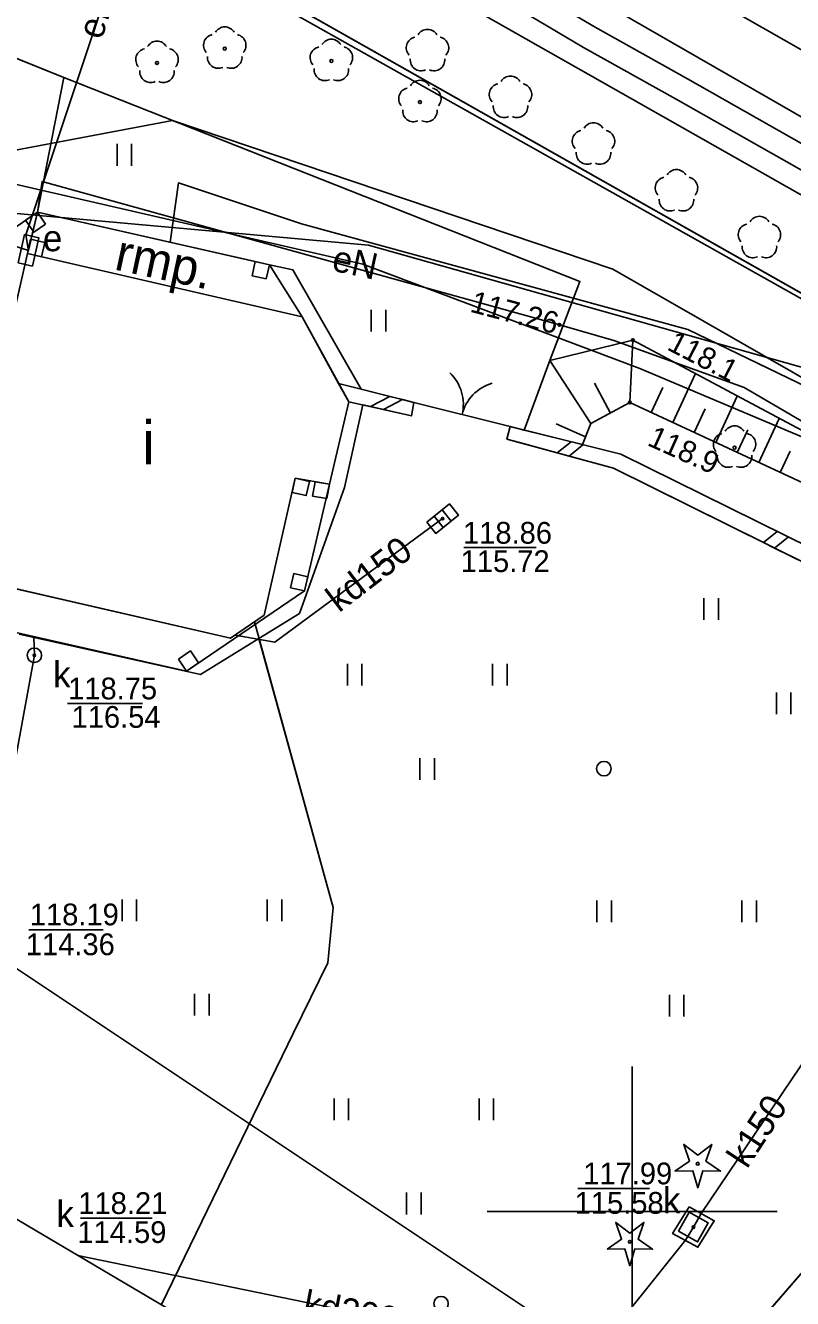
# Model space of a CAD drawing. Extents: x 6434771 to 6436222, y 5663454 to 5664782.
# Drawn here: x 6435079.09 to 6435105.53, y 5663897 to 5663940.88 of the extents above; entities that cross this region are included whole.
import ezdxf

# ---------------------------------------------------------------- set-up
doc = ezdxf.new("R2010")
doc.units = 0
for name, color, linetype in [('Warstwa 1', 7, 'Continuous'), ('Warstwa 10', 7, 'Continuous'), ('Warstwa 11', 7, 'Continuous'), ('Warstwa 12', 7, 'Continuous'), ('Warstwa 13', 7, 'Continuous'), ('Warstwa 14', 7, 'Continuous'), ('Warstwa 15', 7, 'Continuous'), ('Warstwa 2', 7, 'Continuous'), ('Warstwa 20', 7, 'Continuous'), ('Warstwa 21', 7, 'Continuous'), ('Warstwa 3', 7, 'Continuous'), ('Warstwa 31', 7, 'Continuous'), ('Warstwa 32', 7, 'Continuous'), ('Warstwa 33', 7, 'Continuous'), ('Warstwa 4', 7, 'Continuous'), ('Warstwa 5', 7, 'Continuous'), ('Warstwa 51', 7, 'Continuous'), ('Warstwa 6', 7, 'Continuous'), ('Warstwa 63', 7, 'Continuous'), ('Warstwa 7', 7, 'Continuous'), ('Warstwa 8', 7, 'Continuous'), ('Warstwa 9', 7, 'Continuous')]:
    doc.layers.add(name, color=color, linetype=linetype)

msp = doc.modelspace()

# ---------------------------------------------------------------- linework, layer by layer
at = {"layer": 'Warstwa 1'}
msp.add_line((6435069.683, 5663952.11), (6435199.169, 5663878.85), dxfattribs=at)
msp.add_line((6435069.683, 5663952.11), (6435199.169, 5663878.85), dxfattribs=at)
msp.add_lwpolyline([(6435079.153, 5663933.025), (6435076.628, 5663921.954), (6435086.153, 5663919.759), (6435087.322, 5663920.555), (6435088.39, 5663925.272), (6435089.567, 5663925.068), (6435090.232, 5663927.91), (6435088.627, 5663930.84)], close=True, dxfattribs=at)
for centre in [(6435099.029, 5663915.263), (6435093.416, 5663896.82)]:
    msp.add_circle(centre, 0.25, dxfattribs=at)
at = {"layer": 'Warstwa 10'}
for p, q in [((6435097.163, 5663929.329), (6435100.028, 5663930.032)), ((6435099.922, 5663927.883), (6435100.028, 5663930.032)), ((6435100.028, 5663930.032), (6435112.867, 5663923.176)), ((6435096.282, 5663926.934), (6435097.163, 5663929.329)), ((6435097.163, 5663929.329), (6435098.583, 5663927.159)), ((6435101.4, 5663927.195), (6435102.185, 5663928.881)), ((6435099.255, 5663927.522), (6435098.701, 5663928.547)), ((6435100.659, 5663927.54), (6435101.061, 5663928.403)), ((6435098.583, 5663927.159), (6435099.922, 5663927.883)), ((6435099.922, 5663927.883), (6435111.777, 5663922.369)), ((6435102.883, 5663926.506), (6435103.628, 5663928.109)), ((6435102.142, 5663926.851), (6435102.524, 5663927.672)), ((6435098.398, 5663926.698), (6435097.383, 5663927.151)), ((6435098.291, 5663926.435), (6435098.583, 5663927.159)), ((6435104.365, 5663925.816), (6435105.072, 5663927.338)), ((6435096.282, 5663926.934), (6435098.291, 5663926.435)), ((6435103.624, 5663926.161), (6435103.987, 5663926.943)), ((6435105.107, 5663925.472), (6435105.451, 5663926.212))]:
    msp.add_line(p, q, dxfattribs=at)
for points in [[(6435101.48, 5663901.388), (6435101.982, 5663901.735), (6435101.78, 5663902.311), (6435102.265, 5663901.941), (6435102.75, 5663902.311), (6435102.548, 5663901.735), (6435103.05, 5663901.388), (6435102.44, 5663901.402), (6435102.265, 5663900.818), (6435102.09, 5663901.402)], [(6435099.137, 5663898.696), (6435099.639, 5663899.043), (6435099.437, 5663899.619), (6435099.922, 5663899.249), (6435100.407, 5663899.619), (6435100.205, 5663899.043), (6435100.707, 5663898.696), (6435100.097, 5663898.71), (6435099.922, 5663898.126), (6435099.747, 5663898.71)]]:
    msp.add_lwpolyline(points, close=True, dxfattribs=at)
for centre in [(6435102.265, 5663901.643), (6435099.922, 5663898.951)]:
    msp.add_circle(centre, 0.05, dxfattribs=at)
at = {"layer": 'Warstwa 11'}
for centre in [(6435085.959, 5663940.083), (6435083.623, 5663939.591), (6435089.634, 5663939.658), (6435092.687, 5663938.241), (6435103.534, 5663926.329)]:
    msp.add_circle(centre, 0.05, dxfattribs=at)
for centre, start, end in [((6435085.959, 5663940.458), 30.1471, 149.8529), ((6435083.623, 5663939.966), 30.1471, 149.8529), ((6435085.602, 5663940.199), 102.1471, 221.8529), ((6435086.316, 5663940.199), 318.1471, 77.8529), ((6435089.634, 5663940.033), 30.1471, 149.8529), ((6435083.266, 5663939.707), 102.1471, 221.8529), ((6435083.98, 5663939.707), 318.1471, 77.8529), ((6435085.739, 5663939.78), 174.1471, 293.8529), ((6435086.179, 5663939.78), 246.1471, 5.8529), ((6435089.277, 5663939.774), 102.1471, 221.8529), ((6435089.991, 5663939.774), 318.1471, 77.8529), ((6435083.403, 5663939.288), 174.1471, 293.8529), ((6435083.843, 5663939.288), 246.1471, 5.8529), ((6435089.414, 5663939.355), 174.1471, 293.8529), ((6435089.854, 5663939.355), 246.1471, 5.8529), ((6435092.687, 5663938.616), 30.1471, 149.8529), ((6435092.33, 5663938.357), 102.1471, 221.8529), ((6435093.044, 5663938.357), 318.1471, 77.8529), ((6435092.467, 5663937.938), 174.1471, 293.8529), ((6435092.907, 5663937.938), 246.1471, 5.8529), ((6435103.534, 5663926.704), 30.1471, 149.8529), ((6435103.177, 5663926.445), 102.1471, 221.8529), ((6435103.891, 5663926.445), 318.1471, 77.8529), ((6435103.314, 5663926.026), 174.1471, 293.8529), ((6435103.754, 5663926.026), 246.1471, 5.8529)]:
    msp.add_arc(centre, 0.375, start, end, dxfattribs=at)
at = {"layer": 'Warstwa 12'}
for points in [[(6435079.194, 5663933.129), (6435079.1, 5663933.665), (6435082.557, 5663944.054), (6435079.363, 5663945.423), (6435077.427, 5663944.966), (6435072.67, 5663946.544)], [(6435276.296, 5663839.122), (6435202.248, 5663880.463), (6435193.528, 5663885.439), (6435193.106, 5663885.714), (6435192.653, 5663885.899), (6435159.975, 5663904.455), (6435111.809, 5663931.659), (6435087.394, 5663945.495), (6435086.953, 5663945.766), (6435086.601, 5663946.025), (6435086.024, 5663946.382)], [(6435094.917, 5663946.274), (6435142.273, 5663919.31), (6435142.316, 5663919.287), (6435154.155, 5663912.836)], [(6435141.385, 5663916.705), (6435137.435, 5663918.968), (6435135.506, 5663920.019), (6435131.594, 5663922.23), (6435128.874, 5663923.755), (6435124.615, 5663926.134), (6435122.59, 5663927.32), (6435119.795, 5663928.87), (6435117.486, 5663930.176), (6435115.289, 5663931.384), (6435114.334, 5663931.943), (6435109.704, 5663934.552), (6435109.098, 5663934.923), (6435107.886, 5663935.655), (6435101.909, 5663939.037), (6435098.725, 5663940.821), (6435096.535, 5663942.118)], [(6435096.155, 5663941.414), (6435098.325, 5663940.127), (6435101.517, 5663938.339), (6435107.482, 5663934.965), (6435108.682, 5663934.239), (6435109.298, 5663933.862), (6435113.936, 5663931.249), (6435114.895, 5663930.688), (6435117.096, 5663929.478), (6435119.403, 5663928.172), (6435122.194, 5663926.624), (6435124.217, 5663925.44), (6435128.484, 5663923.057), (6435131.202, 5663921.532), (6435135.118, 5663919.319), (6435137.045, 5663918.27), (6435140.991, 5663916.009)], [(6435063.696, 5663930.091), (6435072.471, 5663935.396), (6435084.159, 5663937.604), (6435099.338, 5663932.48), (6435124.367, 5663918.137), (6435165.517, 5663894.728), (6435170.23, 5663892.401), (6435196.432, 5663878.313), (6435197.764, 5663876.037), (6435200.507, 5663874.574)], [(6435036.434, 5663924.72), (6435036.968, 5663924.705), (6435037.38, 5663924.92), (6435043.089, 5663922.25), (6435047.82, 5663923.153), (6435056.168, 5663928.712), (6435062.803, 5663930.732), (6435066.935, 5663932.452), (6435073.955, 5663930.787), (6435075.57, 5663936.138), (6435090.719, 5663932.655), (6435100.267, 5663929.059), (6435106.207, 5663926.557), (6435117.159, 5663920.834), (6435117.521, 5663919.329)], [(6435079.194, 5663933.129), (6435079.5, 5663934.45), (6435079.663, 5663935.508), (6435097.495, 5663930.562), (6435099.368, 5663930.02), (6435103.869, 5663928.405), (6435112.181, 5663923.544), (6435117.365, 5663919.661), (6435117.489, 5663919.58), (6435117.521, 5663919.329)], [(6435084.078, 5663933.415), (6435084.363, 5663935.452), (6435088.606, 5663934.04), (6435101.923, 5663930.399), (6435107.461, 5663927.722), (6435118.142, 5663921.082)], [(6435243.45, 5663833.342), (6435243.347, 5663833.392), (6435243.041, 5663835.668), (6435233.883, 5663842.599), (6435229.544, 5663847.621), (6435230.488, 5663855.43), (6435227.071, 5663861.482), (6435200.606, 5663877.013), (6435196.659, 5663878.93), (6435171.937, 5663892.14), (6435164.739, 5663895.707), (6435120.054, 5663921.259), (6435106.974, 5663928.778), (6435090.917, 5663933.312), (6435076.731, 5663934.584), (6435064.319, 5663933.634), (6435061.286, 5663934.067)], [(6435079.194, 5663933.129), (6435078.218, 5663933.436), (6435076.756, 5663932.533), (6435067.876, 5663934.181), (6435063.696, 5663930.091)]]:
    msp.add_lwpolyline(points, dxfattribs=at)
at = {"layer": 'Warstwa 13'}
for centre in [(6435100.028, 5663930.032), (6435099.922, 5663927.883)]:
    msp.add_circle(centre, 0.045, dxfattribs=at)
for centre, start, end in [((6435092.948, 5663940.373), 30.1471, 149.8529), ((6435092.591, 5663940.114), 102.0477, 221.9513), ((6435093.305, 5663940.114), 318.0487, 77.9523), ((6435092.728, 5663939.695), 174.1984, 293.7229), ((6435093.168, 5663939.695), 246.2771, 5.6877), ((6435095.452, 5663938.503), 102.0477, 221.9513), ((6435095.809, 5663938.762), 30.1471, 149.8529), ((6435096.166, 5663938.503), 318.0487, 77.9523), ((6435095.589, 5663938.084), 174.1984, 293.7229), ((6435096.029, 5663938.084), 246.2771, 5.6877), ((6435098.67, 5663937.152), 30.1471, 149.8529), ((6435098.313, 5663936.893), 102.0477, 221.9513), ((6435099.027, 5663936.893), 318.0487, 77.9523), ((6435098.45, 5663936.474), 174.1984, 293.7229), ((6435098.89, 5663936.474), 246.2771, 5.6877), ((6435101.531, 5663935.54), 30.1471, 149.8529), ((6435101.174, 5663935.281), 102.0477, 221.9513), ((6435101.888, 5663935.281), 318.0487, 77.9523), ((6435101.311, 5663934.862), 174.1984, 293.7229), ((6435101.751, 5663934.862), 246.2771, 5.6877), ((6435104.034, 5663933.669), 102.0477, 221.9513), ((6435104.391, 5663933.928), 30.1471, 149.8529), ((6435104.748, 5663933.669), 318.0487, 77.9523), ((6435104.171, 5663933.25), 174.1984, 293.7229), ((6435104.611, 5663933.25), 246.2771, 5.6877)]:
    msp.add_arc(centre, 0.375, start, end, dxfattribs=at)
at = {"layer": 'Warstwa 14'}
for p, q in [((6435094.197, 5663922.889), (6435096.697, 5663922.889)), ((6435080.541, 5663917.51), (6435083.127, 5663917.51)), ((6435079.207, 5663909.708), (6435081.764, 5663909.708)), ((6435098.127, 5663900.787), (6435100.601, 5663900.787)), ((6435080.985, 5663899.771), (6435083.453, 5663899.771))]:
    msp.add_line(p, q, dxfattribs=at)
for centre in [(6435097.495, 5663930.562), (6435093.469, 5663923.881), (6435079.395, 5663919.171), (6435102.115, 5663899.46)]:
    msp.add_circle(centre, 0.045, dxfattribs=at)
at = {"layer": 'Warstwa 15'}
msp.add_lwpolyline([(6435101.967, 5663900.157), (6435101.396, 5663899.243), (6435102.27, 5663898.763), (6435102.831, 5663899.676)], close=True, dxfattribs=at)
at = {"layer": 'Warstwa 2'}
for points in [[(6435083.106, 5663946.417), (6435083.86, 5663945.988), (6435083.029, 5663944.288), (6435118.054, 5663924.603)], [(6435083.773, 5663896.787), (6435088.328, 5663906.152), (6435089.508, 5663908.568), (6435089.701, 5663910.476), (6435086.979, 5663920.321)]]:
    msp.add_lwpolyline(points, dxfattribs=at)
at = {"layer": 'Warstwa 20'}
for p, q in [((6435098.583, 5663927.159), (6435099.922, 5663927.883)), ((6435099.922, 5663927.883), (6435111.777, 5663922.369)), ((6435098.291, 5663926.435), (6435098.583, 5663927.159))]:
    msp.add_line(p, q, dxfattribs=at)
at = {"layer": 'Warstwa 21'}
for p, q in [((6435097.163, 5663929.329), (6435100.028, 5663930.032)), ((6435100.028, 5663930.032), (6435112.867, 5663923.176)), ((6435096.282, 5663926.934), (6435097.163, 5663929.329))]:
    msp.add_line(p, q, dxfattribs=at)
msp.add_lwpolyline([(6435078.841, 5663932.696), (6435079.06, 5663933.672), (6435079.547, 5663933.562), (6435079.328, 5663932.586), (6435078.841, 5663932.696)], dxfattribs=at)
at = {"layer": 'Warstwa 3'}
msp.add_lwpolyline([(6435092.482, 5663927.883), (6435095.802, 5663927.053)], dxfattribs=at)
for centre, start, end in [((6435092.684, 5663927.822), 346.3587, 46.3587), ((6435095.6, 5663927.114), 106.3587, 166.3587)]:
    msp.add_arc(centre, 1.5, start, end, dxfattribs=at)
at = {"layer": 'Warstwa 31'}
msp.add_lwpolyline([(6435079.153, 5663933.025), (6435079.5, 5663934.45), (6435087.499, 5663932.633), (6435088.307, 5663932.454), (6435090.667, 5663928.345), (6435089.884, 5663928.544), (6435088.627, 5663930.84)], close=True, dxfattribs=at)
at = {"layer": 'Warstwa 33'}
for p, q in [((6435075.325, 5663931.581), (6435079.5, 5663934.45)), ((6435079.5, 5663934.45), (6435087.499, 5663932.633)), ((6435076.628, 5663921.954), (6435079.153, 5663933.025)), ((6435079.153, 5663933.025), (6435088.627, 5663930.84)), ((6435087.499, 5663932.633), (6435088.627, 5663930.84)), ((6435087.322, 5663920.555), (6435088.39, 5663925.272)), ((6435088.39, 5663925.272), (6435089.567, 5663925.068)), ((6435088.713, 5663921.388), (6435089.567, 5663925.068)), ((6435076.628, 5663921.954), (6435086.153, 5663919.759)), ((6435084.639, 5663918.627), (6435088.713, 5663921.388)), ((6435076.281, 5663920.519), (6435084.639, 5663918.627)), ((6435086.153, 5663919.759), (6435087.322, 5663920.555))]:
    msp.add_line(p, q, dxfattribs=at)
for points in [[(6435079.784, 5663934.038), (6435079.372, 5663933.754), (6435079.088, 5663934.166), (6435079.5, 5663934.45)], [(6435079.266, 5663933.512), (6435079.753, 5663933.399), (6435079.64, 5663932.912), (6435079.153, 5663933.025)], [(6435087.388, 5663932.146), (6435086.901, 5663932.257), (6435087.012, 5663932.744), (6435087.499, 5663932.633)], [(6435088.878, 5663925.162), (6435088.768, 5663924.674), (6435088.28, 5663924.784), (6435088.39, 5663925.272)], [(6435089.482, 5663924.575), (6435088.989, 5663924.66), (6435089.074, 5663925.153), (6435089.567, 5663925.068)], [(6435088.226, 5663921.501), (6435088.339, 5663921.988), (6435088.826, 5663921.875), (6435088.713, 5663921.388)], [(6435084.359, 5663919.041), (6435084.773, 5663919.321), (6435085.053, 5663918.907), (6435084.639, 5663918.627)]]:
    msp.add_lwpolyline(points, close=True, dxfattribs=at)
at = {"layer": 'Warstwa 4'}
for p, q in [((6435093.176, 5663923.968), (6435093.488, 5663923.576)), ((6435093.45, 5663924.186), (6435093.762, 5663923.794))]:
    msp.add_line(p, q, dxfattribs=at)
for points in [[(6435092.922, 5663923.765), (6435093.705, 5663924.388), (6435094.016, 5663923.997), (6435093.233, 5663923.374)], [(6435101.605, 5663899.316), (6435101.971, 5663899.97), (6435102.625, 5663899.604), (6435102.259, 5663898.95)]]:
    msp.add_lwpolyline(points, close=True, dxfattribs=at)
msp.add_circle((6435079.395, 5663919.171), 0.25, dxfattribs=at)
at = {"layer": 'Warstwa 5'}
for p, q in [((6435079.5, 5663934.45), (6435080.416, 5663939.09)), ((6435080.416, 5663939.09), (6435098.203, 5663932.054)), ((6435082.246, 5663936.049), (6435082.246, 5663936.799)), ((6435082.746, 5663936.049), (6435082.746, 5663936.799)), ((6435079.5, 5663934.45), (6435087.011, 5663932.744)), ((6435087.011, 5663932.744), (6435087.499, 5663932.633)), ((6435087.499, 5663932.633), (6435088.307, 5663932.454)), ((6435088.307, 5663932.454), (6435090.667, 5663928.345)), ((6435097.163, 5663929.329), (6435098.203, 5663932.054)), ((6435091.008, 5663930.328), (6435091.008, 5663931.078)), ((6435091.508, 5663930.328), (6435091.508, 5663931.078)), ((6435096.282, 5663926.934), (6435097.163, 5663929.329)), ((6435090.667, 5663928.345), (6435091.655, 5663928.094)), ((6435091.655, 5663928.094), (6435092.083, 5663927.985)), ((6435092.083, 5663927.985), (6435092.482, 5663927.883)), ((6435092.396, 5663927.424), (6435092.482, 5663927.883)), ((6435092.482, 5663927.883), (6435095.802, 5663927.053)), ((6435092.482, 5663927.883), (6435095.802, 5663927.053)), ((6435090.086, 5663924.952), (6435090.717, 5663927.801)), ((6435090.717, 5663927.801), (6435090.979, 5663927.742)), ((6435090.979, 5663927.742), (6435091.434, 5663927.64)), ((6435091.434, 5663927.64), (6435092.396, 5663927.424)), ((6435095.687, 5663926.624), (6435095.802, 5663927.053)), ((6435095.802, 5663927.053), (6435096.282, 5663926.934)), ((6435095.687, 5663926.624), (6435096.124, 5663926.505)), ((6435096.124, 5663926.505), (6435097.42, 5663926.151)), ((6435097.42, 5663926.151), (6435097.835, 5663926.037)), ((6435097.835, 5663926.037), (6435099.365, 5663925.619)), ((6435099.365, 5663925.619), (6435104.533, 5663923.058)), ((6435088.533, 5663920.61), (6435090.086, 5663924.952)), ((6435104.533, 5663923.058), (6435104.915, 5663922.868)), ((6435104.915, 5663922.868), (6435110.078, 5663920.31)), ((6435102.478, 5663920.39), (6435102.478, 5663921.14)), ((6435102.978, 5663920.39), (6435102.978, 5663921.14)), ((6435087.136, 5663919.752), (6435088.533, 5663920.61)), ((6435078.874, 5663919.897), (6435085.117, 5663918.511)), ((6435085.117, 5663918.511), (6435087.136, 5663919.752)), ((6435087.136, 5663919.752), (6435089.701, 5663910.476)), ((6435087.136, 5663919.752), (6435089.701, 5663910.476)), ((6435090.189, 5663918.13), (6435090.189, 5663918.88)), ((6435090.689, 5663918.13), (6435090.689, 5663918.88)), ((6435095.189, 5663918.13), (6435095.189, 5663918.88)), ((6435095.689, 5663918.13), (6435095.689, 5663918.88)), ((6435104.978, 5663917.14), (6435104.978, 5663917.89)), ((6435105.478, 5663917.14), (6435105.478, 5663917.89)), ((6435092.689, 5663914.88), (6435092.689, 5663915.63)), ((6435093.189, 5663914.88), (6435093.189, 5663915.63)), ((6435082.421, 5663910.003), (6435082.421, 5663910.753)), ((6435082.921, 5663910.003), (6435082.921, 5663910.753)), ((6435087.421, 5663910.003), (6435087.421, 5663910.753)), ((6435087.921, 5663910.003), (6435087.921, 5663910.753)), ((6435089.508, 5663908.568), (6435089.701, 5663910.476)), ((6435089.508, 5663908.568), (6435089.701, 5663910.476)), ((6435098.788, 5663909.968), (6435098.788, 5663910.718)), ((6435099.288, 5663909.968), (6435099.288, 5663910.718)), ((6435103.788, 5663909.968), (6435103.788, 5663910.718)), ((6435104.288, 5663909.968), (6435104.288, 5663910.718)), ((6435088.328, 5663906.152), (6435089.508, 5663908.568)), ((6435088.328, 5663906.152), (6435089.508, 5663908.568)), ((6435084.921, 5663906.753), (6435084.921, 5663907.503)), ((6435085.421, 5663906.753), (6435085.421, 5663907.503)), ((6435101.288, 5663906.718), (6435101.288, 5663907.468)), ((6435101.788, 5663906.718), (6435101.788, 5663907.468)), ((6435083.773, 5663896.787), (6435088.328, 5663906.152)), ((6435083.773, 5663896.787), (6435088.328, 5663906.152)), ((6435089.727, 5663903.147), (6435089.727, 5663903.897)), ((6435090.227, 5663903.147), (6435090.227, 5663903.897)), ((6435094.727, 5663903.147), (6435094.727, 5663903.897)), ((6435095.227, 5663903.147), (6435095.227, 5663903.897)), ((6435092.227, 5663899.897), (6435092.227, 5663900.647)), ((6435092.727, 5663899.897), (6435092.727, 5663900.647)), ((6435103.04, 5663894.642), (6435106.574, 5663898.72))]:
    msp.add_line(p, q, dxfattribs=at)
at = {"layer": 'Warstwa 51'}
for points in [[(6435089.884, 5663928.544), (6435090.667, 5663928.345), (6435092.482, 5663927.883), (6435092.396, 5663927.424), (6435090.232, 5663927.91), (6435089.884, 5663928.544)], [(6435090.979, 5663927.742), (6435091.655, 5663928.094)], [(6435091.434, 5663927.641), (6435092.083, 5663927.985)], [(6435099.611, 5663926.107), (6435095.802, 5663927.053), (6435095.687, 5663926.624), (6435099.365, 5663925.619)], [(6435097.42, 5663926.151), (6435097.897, 5663926.532)], [(6435097.835, 5663926.037), (6435098.303, 5663926.431)], [(6435099.365, 5663925.619), (6435111.463, 5663919.623), (6435112.259, 5663916.783), (6435113.615, 5663915.617), (6435113.971, 5663916.112), (6435112.772, 5663916.977), (6435111.829, 5663920.068), (6435099.611, 5663926.107)], [(6435104.533, 5663923.058), (6435105.006, 5663923.44)], [(6435104.915, 5663922.868), (6435105.389, 5663923.251)], [(6435107.544, 5663899.839), (6435099.318, 5663890.348), (6435097.256, 5663888.831)]]:
    msp.add_lwpolyline(points, dxfattribs=at)
at = {"layer": 'Warstwa 6'}
for points in [[(6435199.169, 5663878.85), (6435069.683, 5663952.11), (6435070.435, 5663958.091), (6435069.483, 5663961.233), (6435068.325, 5663963.837), (6435062.043, 5663974.514), (6435058.095, 5663979.622), (6435055.831, 5663981.839), (6435050.759, 5663985.791), (6435026.957, 5664002.35), (6434999.334, 5664017.996), (6434991.09, 5664022.666), (6434980.58, 5664028.593), (6434951.952, 5664044.671), (6434942.859, 5664049.431), (6434933.864, 5664054.041), (6434925.132, 5664058.117), (6434918.181, 5664061.441), (6434909.328, 5664065.359), (6434902.911, 5664068.147), (6434896.533, 5664070.874)], [(6435305.06, 5663883.021), (6435273.017, 5663901.219), (6435268.258, 5663903.897), (6435244.547, 5663917.184), (6435243.096, 5663914.681), (6435163.64, 5663959.364), (6435156.428, 5663963.391), (6435120.043, 5663983.972), (6435069.683, 5663952.11), (6435199.169, 5663878.85)], [(6435096.282, 5663926.934), (6435097.163, 5663929.329), (6435098.203, 5663932.054), (6435080.416, 5663939.09), (6435076.246, 5663940.77), (6435077.89, 5663946.481)]]:
    msp.add_lwpolyline(points, dxfattribs=at)
for centre in [(6435093.469, 5663923.881), (6435079.395, 5663919.171), (6435102.115, 5663899.46)]:
    msp.add_circle(centre, 0.045, dxfattribs=at)
at = {"layer": 'Warstwa 63'}
for p, q in [((6435100, 5663905), (6435100, 5663895)), ((6435105, 5663900), (6435095, 5663900))]:
    msp.add_line(p, q, dxfattribs=at)
msp.add_lwpolyline([(6435677.2, 5663546.629), (6436084.093, 5664236.205), (6435222.122, 5664744.822), (6434815.229, 5664055.245)], close=True, dxfattribs=at)
at = {"layer": 'Warstwa 7'}
for points in [[(6435093.469, 5663923.881), (6435087.681, 5663919.621), (6435086.314, 5663919.869)], [(6435079.382, 5663919.785), (6435079.395, 5663919.171), (6435077.564, 5663909.182)], [(6435115.769, 5663916.721), (6435114.085, 5663917.584), (6435113.932, 5663917.043), (6435102.384, 5663899.932), (6435102.115, 5663899.46), (6435101.843, 5663899.008), (6435098.705, 5663895.096), (6435077.564, 5663909.182)], [(6435080.899, 5663898.483), (6435099.899, 5663894.571), (6435104.272, 5663891.498)]]:
    msp.add_lwpolyline(points, dxfattribs=at)
at = {"layer": 'Warstwa 8'}
for p, q in [((6435076.246, 5663940.77), (6435080.416, 5663939.09)), ((6435079.5, 5663934.45), (6435080.416, 5663939.09)), ((6435079.088, 5663934.167), (6435079.5, 5663934.45))]:
    msp.add_line(p, q, dxfattribs=at)
at = {"layer": 'Warstwa 9'}
msp.add_line((6435090.91, 5663946.323), (6435135.707, 5663920.53), dxfattribs=at)

# ---------------------------------------------------------------- texts
at = {"layer": 'Warstwa 13'}
for s, height, rotation, p in [('eNA', 0.9, 72.2958, (6435081.715, 5663940.361)), ('eN', 0.9, 347.7453, (6435089.61, 5663932.441)), ('118.1', 0.75, 332.5905, (6435101.17, 5663929.724)), ('118.9', 0.75, 335.7475, (6435100.489, 5663926.425))]:
    msp.add_text(s, height=height, rotation=rotation, dxfattribs=at).set_placement(p)
at = {"layer": 'Warstwa 14'}
msp.add_text('117.26', height=0.75, rotation=345.1899, dxfattribs=at).set_placement((6435094.381, 5663931.021))
for s, p in [('115.72', (6435094.091, 5663922.04)), ('116.54', (6435080.678, 5663916.671)), ('114.36', (6435079.101, 5663908.833)), ('115.58', (6435098.021, 5663899.919)), ('114.59', (6435080.879, 5663898.912))]:
    msp.add_text(s, height=0.75, dxfattribs=at).set_placement(p)
at = {"layer": 'Warstwa 21'}
msp.add_text('e', height=0.9, dxfattribs=at).set_placement((6435079.69, 5663933.099))
at = {"layer": 'Warstwa 3'}
msp.add_text('i', height=1.5, dxfattribs=at).set_placement((6435083.106, 5663925.751))
at = {"layer": 'Warstwa 32'}
msp.add_text('rmp.', height=1.25, rotation=347.8942, dxfattribs=at).set_placement((6435082.111, 5663932.476))
at = {"layer": 'Warstwa 5'}
for p in [(6435080.042, 5663918.064), (6435101.062, 5663899.93), (6435080.156, 5663899.464)]:
    msp.add_text('k', height=0.9, dxfattribs=at).set_placement(p)
at = {"layer": 'Warstwa 6'}
for s, p in [('118.86', (6435094.172, 5663923.018)), ('118.75', (6435080.559, 5663917.651)), ('118.19', (6435079.239, 5663909.862)), ('117.99', (6435098.317, 5663900.934)), ('118.21', (6435080.91, 5663899.911))]:
    msp.add_text(s, height=0.75, dxfattribs=at).set_placement(p)
at = {"layer": 'Warstwa 7'}
for s, rotation, p in [('kd150', 37.4141, (6435089.896, 5663920.621)), ('k150', 56.677, (6435103.962, 5663901.442)), ('kd200', 349.0573, (6435088.612, 5663896.417))]:
    msp.add_text(s, height=0.9, rotation=rotation, dxfattribs=at).set_placement(p)

doc.saveas('drawing.dxf')
